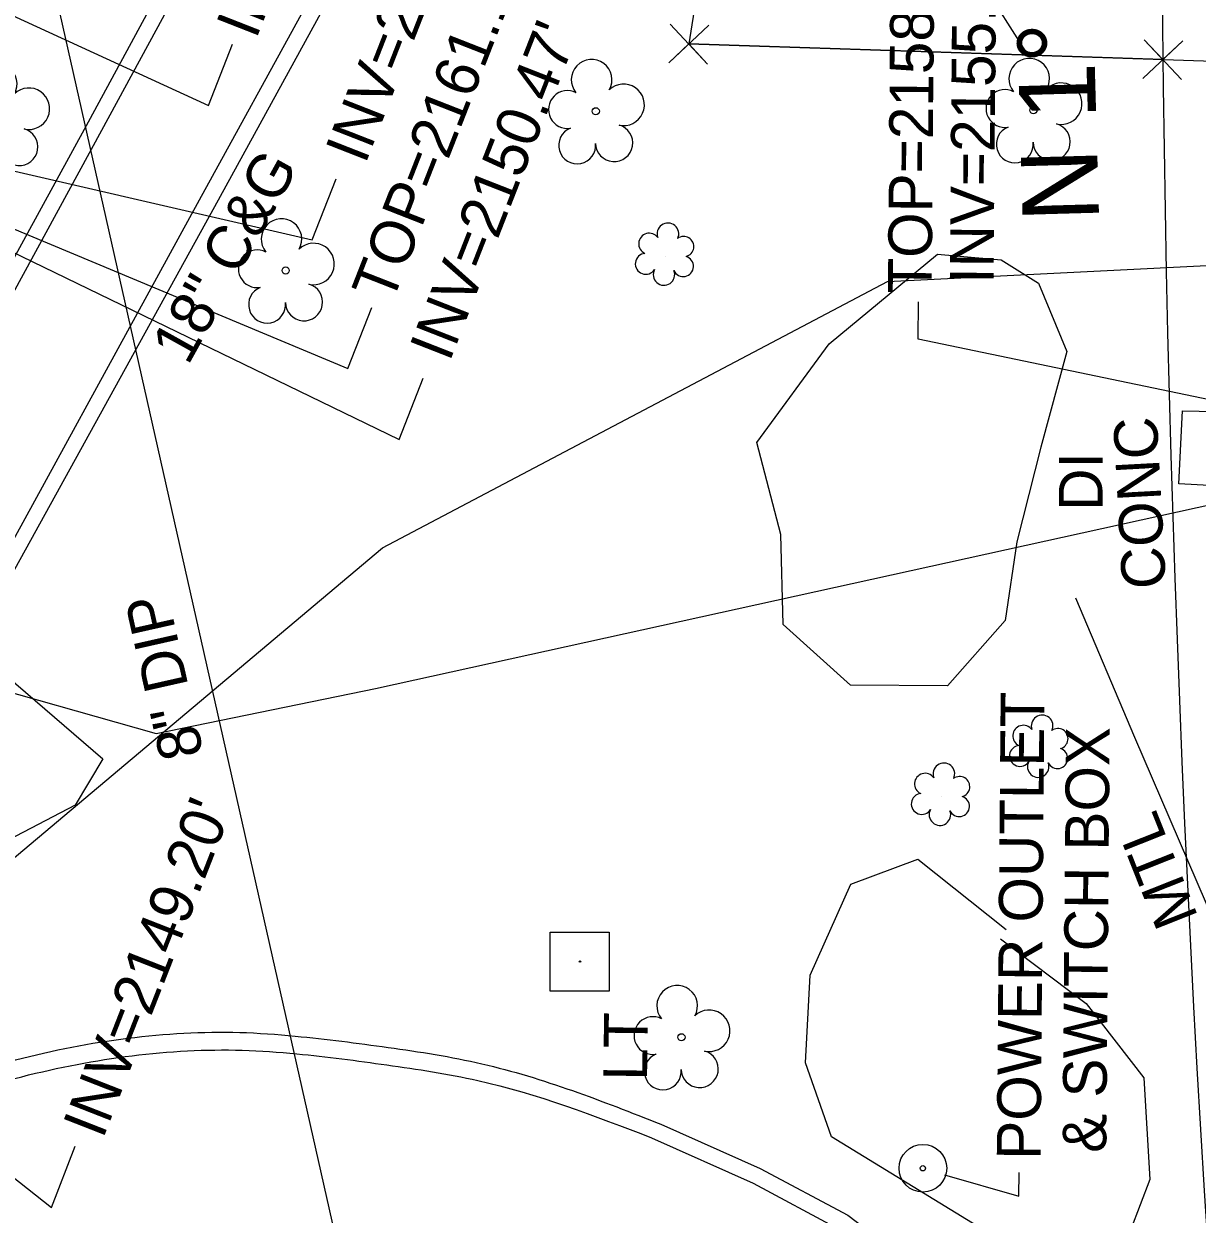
# Model space of a CAD drawing. Extents: x 945964 to 948456, y 631061 to 636061.
# Drawn here: x 946648 to 946755.3, y 632760.1 to 632869 of the extents above; entities that cross this region are included whole.
import ezdxf

# ---------------------------------------------------------------- set-up
doc = ezdxf.new("R2010")
doc.units = 0
for name, color, linetype in [('Exist Boundary County Line', 7, 'Continuous'), ('Exist Guardrail', 7, 'Continuous'), ('Exist Guardrail Text', 7, 'Continuous'), ('Exist Horizontal Baseline Alignment Direction Label', 7, 'Continuous'), ('Exist Other Culture Area Outline', 7, 'Continuous'), ('Exist Other Culture Area Outline Text', 7, 'Continuous'), ('Exist Property Corner CELL', 7, 'Continuous'), ('Exist Property Line', 7, 'Continuous'), ('Exist Property Line Leader', 7, 'Continuous'), ('Exist Right of Way Line', 7, 'Continuous'), ('Exist Roads Curbs', 7, 'Continuous'), ('Exist Roads Curbs Text', 7, 'Continuous'), ('Exist Roads EOP', 7, 'Continuous'), ('Exist Structure Minor Catch Basin Top Elevation', 7, 'Continuous'), ('Exist Structure Minor Drop Inlet Text', 7, 'Continuous'), ('Exist Structure Minor Drop Inlet Top Elevation', 7, 'Continuous'), ('Exist Structure Minor Pipes RCP 15 Inch Invert', 7, 'Continuous'), ('Exist Structure Minor Pipes RCP 18 Inch Invert', 7, 'Continuous'), ('Exist Structure Minor Pipes RCP 24 Inch Invert', 7, 'Continuous'), ('Exist Utilities Other Located Object CELL', 7, 'Continuous'), ('Exist Utilities Other Located Object Leader', 7, 'Continuous'), ('Exist Utilities Other Located Object Text', 7, 'Continuous'), ('Exist Utilities Other Pole With Base CELL', 7, 'Continuous'), ('Exist Utilities Other Pole With Base Text', 7, 'Continuous'), ('Exist Utilities Sanitary Sewer UG Line', 7, 'Continuous'), ('Exist Utilities Sanitary Sewer UG Line Text', 7, 'Continuous'), ('Exist Utilities Telephone UG Cable SUE', 7, 'Continuous'), ('Exist Vegetation Hedge Row', 7, 'Continuous'), ('Exist Vegetation Shrub CELL', 7, 'Continuous'), ('Exist Vegetation Tree CELL', 7, 'Continuous'), ('Exist Vegetation Woods Line', 7, 'Continuous')]:
    doc.layers.add(name, color=color, linetype=linetype)

# ---------------------------------------------------------------- blocks, each defined once
blk = doc.blocks.new('EXIST UTILITIES OTHER LOCATED OBJECT')
at = {"layer": 'Exist Utilities Other Located Object CELL'}
for radius in [0.0436, 0.0048]:
    blk.add_circle((0, 0), radius, dxfattribs=at)
blk = doc.blocks.new('EXIST VEGETATION TREE')
at = {"layer": 'Exist Vegetation Tree CELL'}
blk.add_line((0, 0), (0, 0), dxfattribs=at)
blk.add_circle((0, 0), 0.00652, dxfattribs=at)
for centre, radius, start, end in [((-0.0077, 0.0575), 0.0371, 330.1651, 219.7134), ((0.051, 0.0118), 0.038, 257.1011, 134.1999), ((-0.0521, 0.0031), 0.0345, 62.6636, 279.3457), ((-0.0341, -0.0624), 0.0338, 111.5671, 6.231), ((0.0335, -0.058), 0.034, 181.2822, 74.56)]:
    blk.add_arc(centre, radius, start, end, dxfattribs=at)
blk = doc.blocks.new('EXIST VEGETATION SHRUB')
at = {"layer": 'Exist Vegetation Shrub CELL'}
blk.add_line((0, 0), (0, 0), dxfattribs=at)
for centre, radius, start, end in [((0.0046, 0.0408), 0.0198, 334.8391, 200.4717), ((-0.0297, 0.0225), 0.0194, 35.8908, 245.4216), ((0.0334, 0.0174), 0.0186, 284.4567, 126.0861), ((-0.036, -0.0141), 0.0191, 95.1099, 327.9534), ((0.0327, -0.0186), 0.0187, 204.9913, 73.4601), ((-0.0026, -0.0337), 0.0197, 151.2797, 21.387)]:
    blk.add_arc(centre, radius, start, end, dxfattribs=at)

msp = doc.modelspace()

# ---------------------------------------------------------------- linework, layer by layer
at = {"layer": 'Exist Boundary County Line'}
for p, q in [((946711.59, 632884.52), (946708.83, 632867.13)), ((946708.83, 632867.13), (946851.45, 632862.43))]:
    msp.add_line(p, q, dxfattribs=at)
at = {"layer": 'Exist Guardrail'}
msp.add_lwpolyline([(946786.09, 632606.02), (946784.11, 632618.62), (946779.5, 632652.76), (946776.8, 632680.24), (946773.62, 632720.28), (946771.95, 632747.96), (946771.7, 632750.05), (946765.22, 632765.95), (946756.97, 632786.73), (946749.63, 632803.73), (946744.23, 632816.47)], dxfattribs=at)
at = {"layer": 'Exist Other Culture Area Outline'}
msp.add_line((946753.67, 632826.9), (946754, 632833.6), dxfattribs=at)
msp.add_lwpolyline([(946754, 632833.6), (946760.13, 632833.45), (946759.79, 632826.57), (946753.67, 632826.9)], dxfattribs=at)
at = {"layer": 'Exist Property Corner CELL'}
for p, q in [((946708.83, 632867.13), (946708.83, 632867.13)), ((946752.2, 632865.7), (946752.2, 632865.7))]:
    msp.add_line(p, q, dxfattribs=at)
for points in [[(946710.65, 632868.84), (946707, 632865.42), (946708.83, 632867.13), (946710.54, 632865.3), (946707.12, 632868.95)], [(946750.38, 632863.99), (946754.03, 632867.41), (946752.2, 632865.7), (946750.5, 632867.52), (946753.91, 632863.87)]]:
    msp.add_lwpolyline(points, dxfattribs=at)
at = {"layer": 'Exist Property Line'}
for p in [(946711.59, 632884.52), (946752.2, 632865.7)]:
    msp.add_line(p, (946708.83, 632867.13), dxfattribs=at)
at = {"layer": 'Exist Property Line Leader'}
msp.add_lwpolyline([(946739.87, 632866.11), (946737.03, 632870.62)], dxfattribs=at)
at = {"layer": 'Exist Right of Way Line'}
msp.add_arc((948848.33, 632890.69), 2096.28, 158.90258, 198.31343, dxfattribs=at)
at = {"layer": 'Exist Roads Curbs'}
for points in [[(946693.12, 632932.57), (946672.41, 632894.22), (946653.87, 632859.98), (946633.42, 632822.61), (946613.78, 632790.11), (946601.93, 632772.67)], [(946704.93, 632924.5), (946685.15, 632888.17), (946665.42, 632852.23), (946643.52, 632812.55), (946625.23, 632781.62)], [(946706.28, 632768.36), (946715.37, 632764.32), (946723.38, 632760.03), (946729.96, 632755.05), (946736.31, 632749.23), (946744.84, 632739.34), (946751.41, 632729.22), (946755.7, 632720.14), (946760.54, 632708.81), (946764.21, 632697.09), (946766.49, 632687.88), (946768.02, 632676.08), (946769.73, 632660.88), (946772.17, 632645.55), (946774.65, 632631.96)]]:
    msp.add_lwpolyline(points, dxfattribs=at)
msp.add_spline([(946625.23, 632781.62), (946610.39, 632758.96), (946609.55, 632757.41), (946608.96, 632755.65), (946608.8, 632753.95), (946608.95, 632753.22), (946609.09, 632752.9), (946609.29, 632752.61), (946609.82, 632752.22), (946610.51, 632752.09), (946612.19, 632752.42), (946613.97, 632753.22), (946615.47, 632754.15), (946617.55, 632755.82), (946619.49, 632757.73), (946623.22, 632761.9), (946627.2, 632765.89), (946629.47, 632767.58), (946630.7, 632768.31), (946632, 632768.94), (946642.15, 632772.77), (946652.39, 632775.41), (946662.64, 632776.68), (946667.74, 632776.75), (946672.82, 632776.41), (946681.32, 632775.38), (946689.91, 632773.88), (946706.28, 632768.36)], degree=3, dxfattribs=at)
at = {"layer": 'Exist Roads EOP'}
for points in [[(946694.36, 632931.72), (946674.23, 632894.43), (946655.11, 632859.22), (946634.68, 632821.78), (946614.79, 632789.02), (946605.08, 632774.36), (946605.81, 632773.79), (946604.02, 632771.14), (946603.2, 632771.71)], [(946703.67, 632925.27), (946683.74, 632888.72), (946664.03, 632852.86), (946642.37, 632813.34), (946624.15, 632782.33)], [(946705.43, 632767.12), (946714.71, 632762.97), (946722.57, 632758.76), (946729, 632753.89), (946735.23, 632748.18), (946743.64, 632738.44), (946750.1, 632728.49), (946754.33, 632719.53), (946759.13, 632708.29), (946762.77, 632696.69), (946765.01, 632687.6), (946766.53, 632675.9), (946768.25, 632660.68), (946770.69, 632645.3), (946773.24, 632631.64)]]:
    msp.add_lwpolyline(points, dxfattribs=at)
msp.add_spline([(946624.15, 632782.33), (946609.23, 632759.71), (946608.22, 632757.71), (946607.61, 632755.41), (946607.6, 632753.2), (946607.89, 632752.24), (946608.12, 632751.82), (946608.41, 632751.44), (946609.15, 632750.93), (946610.07, 632750.73), (946612.24, 632751.08), (946614.5, 632752.05), (946616.43, 632753.2), (946618.49, 632754.81), (946620.42, 632756.67), (946624.12, 632760.76), (946628.07, 632764.68), (946630.3, 632766.33), (946631.51, 632767.03), (946632.8, 632767.64), (946642.79, 632771.3), (946652.87, 632773.83), (946662.95, 632775.06), (946667.97, 632775.12), (946672.96, 632774.79), (946681.21, 632773.78), (946689.52, 632772.36), (946705.43, 632767.12)], degree=3, dxfattribs=at)
at = {"layer": 'Exist Structure Minor Catch Basin Top Elevation'}
msp.add_lwpolyline([(946627.05, 632858.57), (946677.64, 632837.47), (946679.83, 632843.05)], dxfattribs=at)
at = {"layer": 'Exist Structure Minor Pipes RCP 15 Inch Invert'}
msp.add_lwpolyline([(946627.47, 632860.04), (946674.38, 632849.22), (946676.56, 632854.8)], dxfattribs=at)
at = {"layer": 'Exist Structure Minor Pipes RCP 18 Inch Invert'}
for points in [[(946643.88, 632871.17), (946664.88, 632861.52), (946667.07, 632867.11)], [(946627.4, 632857.57), (946682.33, 632830.97), (946684.52, 632836.56)], [(946605.11, 632796.66), (946650.51, 632760.75), (946652.7, 632766.34)]]:
    msp.add_lwpolyline(points, dxfattribs=at)
at = {"layer": 'Exist Structure Minor Pipes RCP 24 Inch Invert'}
msp.add_lwpolyline([(946756.47, 632834.6), (946729.82, 632840.13), (946729.84, 632843.55)], dxfattribs=at)
at = {"layer": 'Exist Utilities Other Located Object Leader'}
msp.add_lwpolyline([(946732.24, 632763.73), (946739.04, 632761.79), (946739.06, 632763.94)], dxfattribs=at)
at = {"layer": 'Exist Utilities Other Pole With Base CELL'}
msp.add_line((946698.87, 632783.23), (946698.87, 632783.23), dxfattribs=at)
msp.add_lwpolyline([(946696.15, 632785.93), (946701.55, 632785.93), (946701.55, 632780.53), (946696.15, 632780.53), (946696.15, 632785.93)], dxfattribs=at)
msp.add_circle((946698.87, 632783.23), 0.0707, dxfattribs=at)
at = {"layer": 'Exist Utilities Sanitary Sewer UG Line'}
msp.add_lwpolyline([(946679.18, 632746.23), (946648.81, 632881.02)], dxfattribs=at)
at = {"layer": 'Exist Utilities Telephone UG Cable SUE'}
for points in [[(946641.97, 632809.2), (946660.11, 632804.07), (946680.18, 632808.2), (946774.58, 632828.99), (946817.48, 632831.3), (946823.43, 632884.78), (946845.89, 632888.04), (946847.42, 632888.16), (946852.01, 632876.88), (946848.99, 632861.62)], [(946636.81, 632795.11), (946643.64, 632789.82), (946680.82, 632821.06), (946727, 632845.41), (946759.9, 632847.07), (946808.05, 632859.72), (946846.96, 632864.02), (946847.96, 632862.19)]]:
    msp.add_lwpolyline(points, dxfattribs=at)
at = {"layer": 'Exist Vegetation Hedge Row'}
for points in [[(946631.73, 632781.09), (946636.02, 632772.68), (946627.68, 632767.14), (946620.7, 632761.74), (946614.81, 632756.5), (946612.94, 632754.6), (946610.33, 632755.19), (946615.26, 632763.87), (946626.78, 632782.34), (946644.56, 632810.92), (946655.21, 632801.76), (946652.68, 632797.52), (946643.85, 632792.93), (946630.68, 632782.76)], [(946749.35, 632755.23), (946745.64, 632752.67), (946721.89, 632767.19), (946719.51, 632773.98), (946719.95, 632782), (946723.67, 632790.32), (946729.78, 632792.58), (946737.88, 632786.15)], [(946737.36, 632785.3), (946745.19, 632779.38), (946750.48, 632772.59), (946751.01, 632763.31), (946748.37, 632756.35), (946748.37, 632756.35)]]:
    msp.add_lwpolyline(points, dxfattribs=at)
at = {"layer": 'Exist Vegetation Shrub CELL'}
msp.add_line((946706.69, 632847.73), (946706.69, 632847.73), dxfattribs=at)
for centre, radius, start, end in [((946706.92, 632849.77), 0.99, 334.8391, 200.4717), ((946705.21, 632848.86), 0.968, 35.8908, 245.4216), ((946708.36, 632848.6), 0.929, 284.4567, 126.0861), ((946704.89, 632847.03), 0.955, 95.1099, 327.9534), ((946708.32, 632846.8), 0.937, 204.9913, 73.4601), ((946706.56, 632846.05), 0.984, 151.2797, 21.387)]:
    msp.add_arc(centre, radius, start, end, dxfattribs=at)
at = {"layer": 'Exist Vegetation Tree CELL'}
for p, q in [((946700.32, 632860.98), (946700.32, 632860.98)), ((946740.36, 632861.08), (946740.36, 632861.08)), ((946708.16, 632776.31), (946708.16, 632776.31))]:
    msp.add_line(p, q, dxfattribs=at)
for centre in [(946700.32, 632860.98), (946740.36, 632861.08), (946708.16, 632776.31)]:
    msp.add_circle(centre, 0.326, dxfattribs=at)
for centre, radius, start, end in [((946699.94, 632863.86), 1.86, 330.1651, 219.7134), ((946739.98, 632863.95), 1.86, 330.1651, 219.7134), ((946702.87, 632861.57), 1.9, 257.1011, 134.1999), ((946742.91, 632861.67), 1.9, 257.1011, 134.1999), ((946697.72, 632861.14), 1.73, 62.6636, 279.3457), ((946737.76, 632861.23), 1.73, 62.6636, 279.3457), ((946698.62, 632857.86), 1.69, 111.5671, 6.231), ((946702, 632858.08), 1.7, 181.2822, 74.56), ((946738.66, 632857.96), 1.69, 111.5671, 6.231), ((946742.03, 632858.18), 1.7, 181.2822, 74.56), ((946707.77, 632779.18), 1.86, 330.1651, 219.7134), ((946710.7, 632776.9), 1.9, 257.1011, 134.1999), ((946705.55, 632776.46), 1.73, 62.6636, 279.3457), ((946709.83, 632773.41), 1.7, 181.2822, 74.56), ((946706.45, 632773.19), 1.69, 111.5671, 6.231)]:
    msp.add_arc(centre, radius, start, end, dxfattribs=at)
at = {"layer": 'Exist Vegetation Woods Line'}
msp.add_lwpolyline([(946740.82, 632845.26), (946743.42, 632839.02), (946741.05, 632830.25), (946738.84, 632821.62), (946737.77, 632814.43), (946732.49, 632808.44), (946723.64, 632808.5), (946717.46, 632814.06), (946717.25, 632822.28), (946715.06, 632830.68), (946721.68, 632839.7), (946731.58, 632847.92), (946737.4, 632847.38), (946740.82, 632845.26)], dxfattribs=at)

# ---------------------------------------------------------------- block references
at = {"layer": 'Exist Utilities Other Located Object CELL', "xscale": 50, "yscale": 50}
msp.add_blockref('EXIST UTILITIES OTHER LOCATED OBJECT', (946730.25, 632764.33), dxfattribs=at)
at = {"layer": 'Exist Vegetation Shrub CELL', "xscale": 50, "yscale": 50}
for p in [(946740.93, 632802.74), (946731.94, 632798.35)]:
    msp.add_blockref('EXIST VEGETATION SHRUB', p, dxfattribs=at)
at = {"layer": 'Exist Vegetation Tree CELL', "xscale": 50, "yscale": 50}
for p in [(946645.9, 632860.62), (946671.95, 632846.42)]:
    msp.add_blockref('EXIST VEGETATION TREE', p, dxfattribs=at)

# ---------------------------------------------------------------- texts
at = {"layer": 'Exist Guardrail Text'}
msp.add_text('MTL', height=4, rotation=111.6434, dxfattribs=at).set_placement((946755.47, 632787.29))
at = {"layer": 'Exist Horizontal Baseline Alignment Direction Label'}
msp.add_text('N 1%%d 37\' 13.0" W', height=7, rotation=91.6203, dxfattribs=at).set_placement((946746.38, 632850.94))
at = {"layer": 'Exist Other Culture Area Outline Text'}
msp.add_text('CONC', height=4, rotation=93.0933, dxfattribs=at).set_placement((946752.5, 632817.4))
at = {"layer": 'Exist Roads Curbs Text'}
msp.add_text('18" C&G', height=4, rotation=60.9039, dxfattribs=at).set_placement((946663, 632837.65))
at = {"layer": 'Exist Structure Minor Catch Basin Top Elevation'}
msp.add_text("TOP=2161.16'", height=4, rotation=68.6189, dxfattribs=at).set_placement((946681.65, 632843.31))
at = {"layer": 'Exist Structure Minor Drop Inlet Text'}
msp.add_text('DI', height=4, rotation=90, dxfattribs=at).set_placement((946746.69, 632824.45))
at = {"layer": 'Exist Structure Minor Drop Inlet Top Elevation'}
msp.add_text("TOP=2158.58'", height=4, rotation=89.5466, dxfattribs=at).set_placement((946731.05, 632844.29))
at = {"layer": 'Exist Structure Minor Pipes RCP 15 Inch Invert'}
for s, rotation, p in [("INV=2150.71'", 68.6189, (946679.22, 632856.04)), ("INV=2155.40'", 89.5187, (946736.71, 632845.2))]:
    msp.add_text(s, height=4, rotation=rotation, dxfattribs=at).set_placement(p)
at = {"layer": 'Exist Structure Minor Pipes RCP 18 Inch Invert'}
for s, p in [("INV=2154.91'", (946669.23, 632867.47)), ("INV=2150.47'", (946686.93, 632837.96)), ("INV=2149.20'", (946655.21, 632766.91))]:
    msp.add_text(s, height=4, rotation=68.6189, dxfattribs=at).set_placement(p)
at = {"layer": 'Exist Utilities Other Located Object Text'}
for s, p in [('POWER OUTLET', (946741.01, 632765.09)), ('& SWITCH BOX', (946747.02, 632765.73))]:
    msp.add_text(s, height=4, rotation=89.5187, dxfattribs=at).set_placement(p)
at = {"layer": 'Exist Utilities Other Pole With Base Text'}
msp.add_text('LT', height=4, rotation=89.3558, dxfattribs=at).set_placement((946705.01, 632772.32))
at = {"layer": 'Exist Utilities Sanitary Sewer UG Line Text'}
msp.add_text('8" DIP', height=4, rotation=102.6945, dxfattribs=at).set_placement((946664.46, 632802.21))

doc.saveas('drawing.dxf')
